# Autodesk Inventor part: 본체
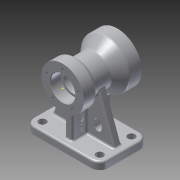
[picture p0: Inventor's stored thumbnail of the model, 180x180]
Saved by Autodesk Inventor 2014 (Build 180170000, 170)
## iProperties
Created: 2015-08
Part Number: 본체
Material: 알루미늄 6061
Document SubType Name: Modeling
Designer: USER
Density: 2.71 g/cm^3
Appearance: 알루미늄 - 평지
Mass: 1057.68 g
Surface Area: 750.556 cm^2
Volume: 390.289 cm^3
Author: USER
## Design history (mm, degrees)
sketch "스케치1"
  geometry: C1 r 26 at (0, 0); 1 further point
  constraints: 1 centre point, 1 coincident
  dimensions: "d1" = 52 diameter of C1
extrude "돌출1" new body sketch "스케치1" distance "d2" = 90; taper "d3" = 0 deg
sketch "스케치2"
  geometry: C1 r 26 at (0, 0) reference; C2 r 35 at (0, 0)
  constraints: 1 centre point, 1 coincident
  dimensions: "d4" = 70 diameter of C2
extrude "돌출2" join sketch "스케치2" distance "d5" = 20; taper "d6" = 0 deg
sketch "스케치3"
  geometry: C1 r 26 at (0, 0) reference; C2 r 40 at (0, 0)
  constraints: 1 centre point, 1 coincident
  dimensions: "d7" = 80 diameter of C2
extrude "돌출3" join sketch "스케치3" distance "d8" = 20; taper "d9" = 0 deg
node "작업축1"
node "작업 평면1"
sketch "스케치5"
  geometry: L1 (20, -35)-(20, 35) reference; L2 (20, 26)-(70, 26) reference; L3 (70, 40)-(70, -40) reference; L4 (20, 35)-(25.196, 26); L5 (70, 40)-(53.315, 26); L6 (25.196, 26)-(20, 26); L7 (20, 35)-(20, 26); L8 (53.315, 26)-(70, 26); L9 (70, 40)-(70, 26); L10 (-18, 0)-(108, 0) reference; 1 further point
  constraints: 12 end point, 3 point on line, 2 perpendicular
revolve "회전1" sketch "스케치5" stored, may be unused: angle "d13" = 90 deg
sketch "스케치6"
  geometry: C1 r 35 at (0, 0) reference; C2 r 20 at (0, 0)
  constraints: 1 centre point, 1 coincident
  dimensions: "d14" = 40 diameter of C2
extrude "돌출4" cut sketch "스케치6" distance "d15" = 17; taper "d16" = 0 deg
sketch "스케치7"
  geometry: C1 r 20 at (0, 0) reference; C2 r 16 at (0, 0)
  constraints: 1 centre point, 1 coincident
  dimensions: "d17" = 32 diameter of C2
extrude "돌출5" cut sketch "스케치7" stored distance "d18" = 17; taper "d19" = 0 deg
sketch "스케치8"
  geometry: C1 r 16 at (0, 0) reference; C2 r 40 at (0, 0) reference; C3 r 26 at (0, 0)
  constraints: 1 centre point, 1 coincident
  dimensions: "d20" = 52 diameter of C3
extrude "돌출6" cut sketch "스케치8" distance "d21" = 20; taper "d22" = 0 deg
sketch "스케치10"
  geometry: 1 further point
hole "구멍1" sketch "스케치10" at (0, 27) diameter "d27" = 3.459; stored, may be unused: countersink angle "d31" = 90 deg, drill point angle "d33" = 118 deg; dims "d28" = 10, "d29" = 4, "d30" = 2, "d32" = 13
sketch "스케치12"
  geometry: 1 further point
hole "구멍2" sketch "스케치12" at (0, -33) diameter "d39" = 3.459; stored, may be unused: countersink angle "d43" = 90 deg, drill point angle "d45" = 118 deg; dims "d40" = 10, "d41" = 4, "d42" = 2, "d44" = 13
node "작업 평면3"
  node "작업 평면2"
sketch "스케치13"
  geometry: L1 (-18, 0)-(108, 0) reference; L2 (80, -61)-(80, 61); L3 (0, 61)-(80, 61); L4 (0, -61)-(80, -61); L5 (0, 61)-(0, -61)
  constraints: 8 end point, 2 parallel, 1 perpendicular
extrude "돌출8" join sketch "스케치13" distance "d54" = 12; taper "d55" = 0 deg
sketch "스케치14"
  geometry: L1 (-61, 80)-(-61, 0) reference; C1 r 6 at (-47, 14); C2 r 6 at (-44.946, 64.554); C3 r 6 at (47, 14); C4 r 6 at (47, 66); 2 further points
  constraints: 4 centre point, 1 midpoint
  dimensions: "d58" = 12 diameter of C1; "d59" = 12 diameter of C2; "d60" = 12 diameter of C3; "d61" = 12 diameter of C4
extrude "돌출9" cut sketch "스케치14" distance "d62" = 12; taper "d63" = 0 deg
sketch "스케치15"
  geometry: L1 (10, -26.328)-(10, -78); L2 (10, -78)-(70, -78); L3 (70, -78)-(77.678, -34.454); L4 (10, -26.328)-(28.42, -21.116); L5 (28.42, -21.116)-(65.452, -21.116); L6 (65.452, -21.116)-(70, -33.1); L7 (70, -33.1)-(77.678, -34.454); 1 further point
  constraints: 14 end point, 2 perpendicular, 1 vertical
extrude "돌출10" join sketch "스케치15" stored distance "d67" = 12; taper "d68" = 0 deg
node "작업 평면4"
sketch "스케치16"
  geometry: L1 (36.897, 85.898)-(10, 12); L2 (0, 0)-(0, 12) reference; L3 (85.103, 85.898)-(112, 12); L4 (10, 4.344)-(112, 4.344); L5 (112, 12)-(112, 4.344); L6 (10, 12)-(10, 4.344); A1 r 24.45 centre (61, 90) between (36.897, 85.898) and (85.103, 85.898); 1 further point
  constraints: 10 end point, 2 point on circle, 1 centre point, 1 coincident, 1 parallel
extrude "돌출11" join sketch "스케치16" stored distance "d71" = 12; taper "d72" = 0 deg
sketch "스케치17"
  geometry: 2 further points
  constraints: 1 other
feature "엠보싱1" sketch "스케치17" dims "d1" = 52, "d75" = 0.5, "d76" = 0
fillet "모깎기1" dims "d77" = 5
fillet "모깎기2" dims "d78" = 3
fillet "모깎기3" dims "d79" = 3
sketch "스케치19"
  geometry: 1 further point
sketch "스케치20"
  geometry: 1 further point
sketch "스케치21"
  geometry: C1 r 16 at (0, 0) reference; C2 r 26 at (0, 0) reference; C3 r 19 at (0, 0)
  constraints: 1 centre point, 1 coincident
  dimensions: "d83" = 38 diameter of C3
extrude "돌출12" cut sketch "스케치21" distance "d84" = 3; taper "d85" = 0 deg
fillet "모깎기4" dims "d86" = 3
fillet "모깎기5" dims "d87" = 14
fillet "모깎기6" dims "d88" = 0.3
fillet "모깎기7" dims "d89" = 3
chamfer "모따기1" distance "d90" = 1; stored, may be unused: second distance "d91" = 2, angle "d92" = 45 deg
fillet "모깎기8" dims "d93" = 3
sketch "스케치24"
  geometry: L1 (85, 42)-(85, 42); L2 (91, 36)-(91, 30); L3 (85, 24)-(85, 24); L4 (79, 30)-(79, 36); A1 r 6 centre (85, 36) between (85, 42) and (79, 36); A2 r 6 centre (85, 36) between (91, 36) and (85, 42); A3 r 6 centre (85, 30) between (85, 24) and (91, 30); A4 r 6 centre (85, 30) between (79, 30) and (85, 24)
  constraints: 8 end point, 8 point on circle, 8 tangent, 4 centre point, 3 equal radius, 2 parallel, 1 horizontal, 1 perpendicular
extrude "돌출14" cut sketch "스케치24" stored distance "d107" = 10; taper "d108" = 0 deg
node "솔리드1"
pattern_circular "원형 패턴1" dims angle "d35" = 360 deg
pattern_circular "원형 패턴2" dims angle "d47" = 360 deg
mirror "대칭2"
other parameters: "d10" = 0, "d49" = 0, "d94" = 24
